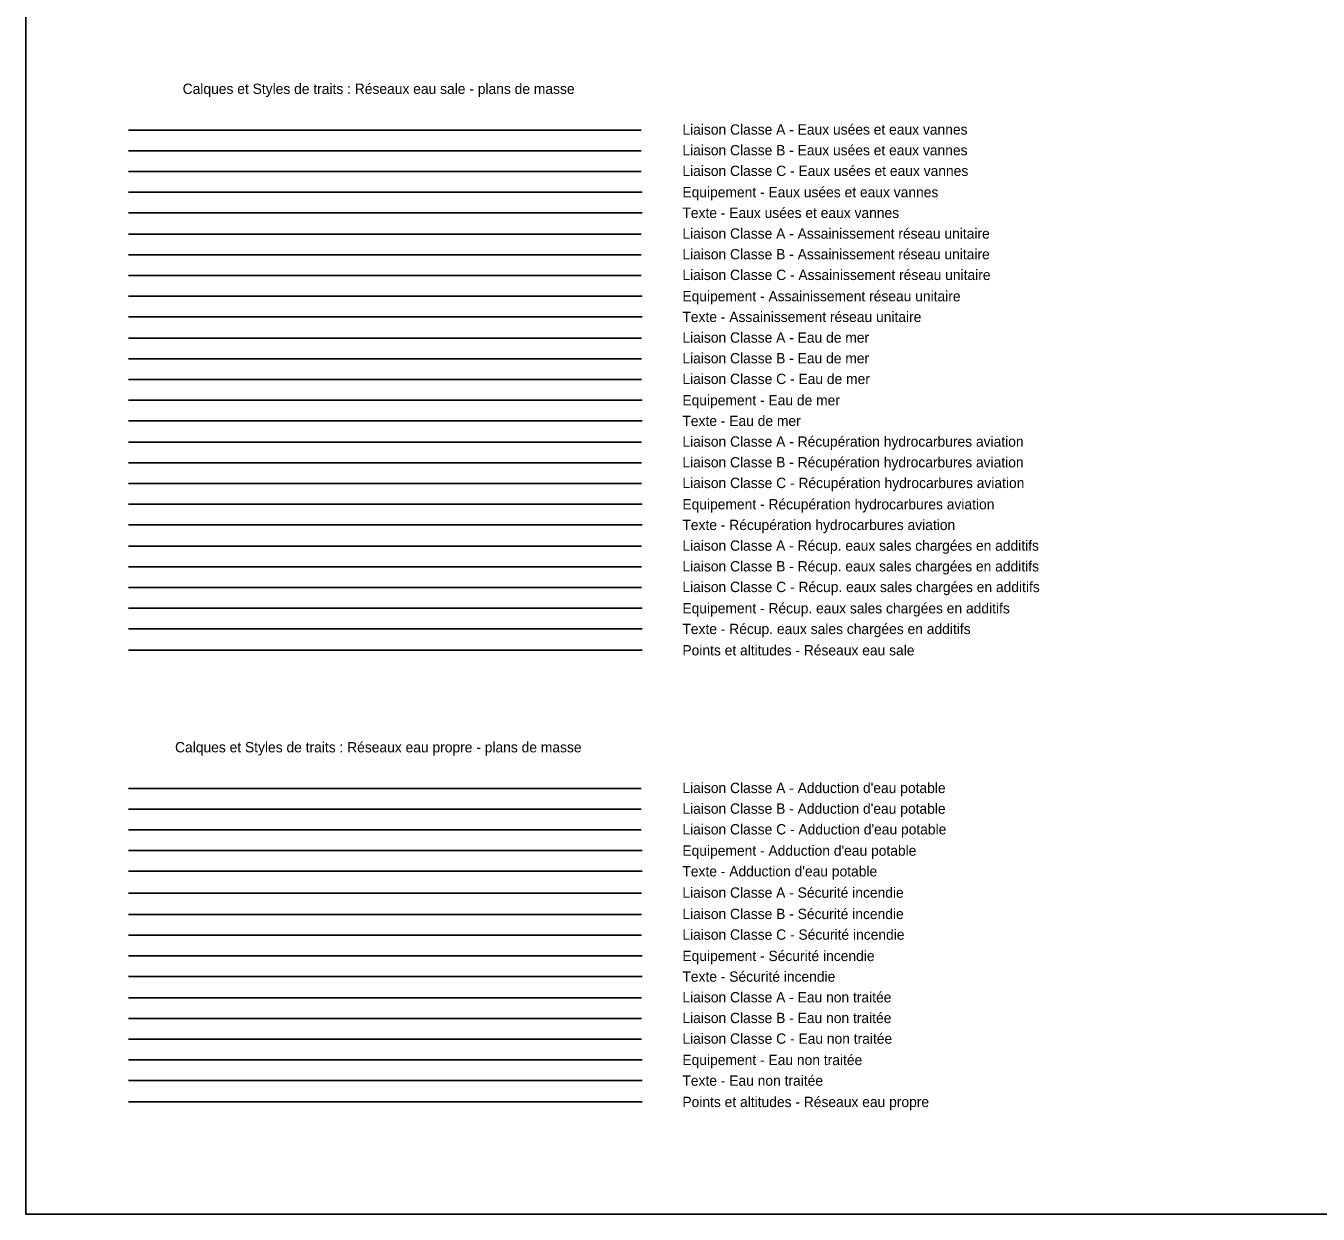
# Model space of a CAD drawing. Extents: x 703432 to 707394, y 7057985 to 7059523.
# Drawn here: x 707199.5 to 707262, y 7058419.6 to 7058477 of the extents above; entities that cross this region are included whole.
import ezdxf

# ---------------------------------------------------------------- set-up
doc = ezdxf.new("R2010")
doc.units = 0
for name, color, linetype in [('DH_CADRE -CARTOUCHE', 7, 'Continuous'), ('R_EPR_AEP_CANALISATION_CL_A', 7, 'Continuous'), ('R_EPR_AEP_CANALISATION_CL_B', 7, 'Continuous'), ('R_EPR_AEP_CANALISATION_CL_C', 7, 'Continuous'), ('R_EPR_AEP_EQUIP', 7, 'Continuous'), ('R_EPR_AEP_TEXTE', 7, 'Continuous'), ('R_EPR_EAU_NON_TRAITEE_CANALISATION_CL_A', 7, 'Continuous'), ('R_EPR_EAU_NON_TRAITEE_CANALISATION_CL_B', 7, 'Continuous'), ('R_EPR_EAU_NON_TRAITEE_CANALISATION_CL_C', 7, 'Continuous'), ('R_EPR_EAU_NON_TRAITEE_EQUIP', 7, 'Continuous'), ('R_EPR_EAU_NON_TRAITEE_TEXTE', 7, 'Continuous'), ('R_EPR_EAU_PROPRE_ALT_POINT', 7, 'Continuous'), ('R_EPR_INCENDIE_CANALISATION_CL_A', 7, 'Continuous'), ('R_EPR_INCENDIE_CANALISATION_CL_B', 7, 'Continuous'), ('R_EPR_INCENDIE_CANALISATION_CL_C', 7, 'Continuous'), ('R_EPR_INCENDIE_EQUIP', 7, 'Continuous'), ('R_EPR_INCENDIE_TEXTE', 7, 'Continuous'), ('R_ES_EAU_SALE_ALT_POINT', 7, 'Continuous'), ('R_ES_EU_CANALISATION_CL_A', 7, 'Continuous'), ('R_ES_EU_CANALISATION_CL_B', 7, 'Continuous'), ('R_ES_EU_CANALISATION_CL_C', 7, 'Continuous'), ('R_ES_EU_EQUIP', 7, 'Continuous'), ('R_ES_EU_TEXTE', 7, 'Continuous'), ('R_ES_HYDROCARB_CANA_CL_A', 7, 'Continuous'), ('R_ES_HYDROCARB_CANA_CL_B', 7, 'Continuous'), ('R_ES_HYDROCARB_CANA_CL_C', 7, 'Continuous'), ('R_ES_HYDROCARB_EQUIP', 7, 'Continuous'), ('R_ES_HYDROCARB_TEXTE', 7, 'Continuous'), ('R_ES_INCENDIE_CANA_CL_A', 7, 'Continuous'), ('R_ES_INCENDIE_CANA_CL_B', 7, 'Continuous'), ('R_ES_INCENDIE_CANA_CL_C', 7, 'Continuous'), ('R_ES_INCENDIE_EQUIP', 7, 'Continuous'), ('R_ES_INCENDIE_TEXTE', 7, 'Continuous'), ('R_ES_MER_CANALISATION_CL_A', 7, 'Continuous'), ('R_ES_MER_CANALISATION_CL_B', 7, 'Continuous'), ('R_ES_MER_CANALISATION_CL_C', 7, 'Continuous'), ('R_ES_MER_EQUIP', 7, 'Continuous'), ('R_ES_MER_TEXTE', 7, 'Continuous'), ('R_ES_UNITAIRE_CANALISATION_CL_A', 7, 'Continuous'), ('R_ES_UNITAIRE_CANALISATION_CL_B', 7, 'Continuous'), ('R_ES_UNITAIRE_CANALISATION_CL_C', 7, 'Continuous'), ('R_ES_UNITAIRE_EQUIP', 7, 'Continuous'), ('R_ES_UNITAIRE_TEXTE', 7, 'Continuous')]:
    doc.layers.add(name, color=color, linetype=linetype)

msp = doc.modelspace()

# ---------------------------------------------------------------- linework, layer by layer
at = {"layer": 'DH_CADRE -CARTOUCHE'}
msp.add_lwpolyline([(707199.469, 7058644.551), (707324.469, 7058644.551), (707324.469, 7058419.551), (707199.469, 7058419.551)], close=True, dxfattribs=at)
at = {"layer": 'R_EPR_AEP_CANALISATION_CL_A'}
msp.add_line((707204.439, 7058440.135), (707229.225, 7058440.135), dxfattribs=at)
at = {"layer": 'R_EPR_AEP_CANALISATION_CL_B'}
msp.add_line((707204.439, 7058439.135), (707229.225, 7058439.135), dxfattribs=at)
at = {"layer": 'R_EPR_AEP_CANALISATION_CL_C'}
msp.add_line((707204.439, 7058438.135), (707229.225, 7058438.135), dxfattribs=at)
at = {"layer": 'R_EPR_AEP_EQUIP'}
msp.add_line((707204.439, 7058437.135), (707229.269, 7058437.135), dxfattribs=at)
at = {"layer": 'R_EPR_AEP_TEXTE'}
msp.add_line((707204.439, 7058436.135), (707229.269, 7058436.135), dxfattribs=at)
at = {"layer": 'R_EPR_EAU_NON_TRAITEE_CANALISATION_CL_A'}
msp.add_line((707204.439, 7058430.011), (707229.24, 7058430.011), dxfattribs=at)
at = {"layer": 'R_EPR_EAU_NON_TRAITEE_CANALISATION_CL_B'}
msp.add_line((707204.439, 7058429.011), (707229.24, 7058429.011), dxfattribs=at)
at = {"layer": 'R_EPR_EAU_NON_TRAITEE_CANALISATION_CL_C'}
msp.add_line((707204.439, 7058428.011), (707229.24, 7058428.011), dxfattribs=at)
at = {"layer": 'R_EPR_EAU_NON_TRAITEE_EQUIP'}
msp.add_line((707204.439, 7058427.011), (707229.269, 7058427.011), dxfattribs=at)
at = {"layer": 'R_EPR_EAU_NON_TRAITEE_TEXTE'}
msp.add_line((707204.439, 7058426.011), (707229.269, 7058426.011), dxfattribs=at)
at = {"layer": 'R_EPR_EAU_PROPRE_ALT_POINT'}
msp.add_line((707204.439, 7058424.98), (707229.269, 7058424.98), dxfattribs=at)
at = {"layer": 'R_EPR_INCENDIE_CANALISATION_CL_A'}
msp.add_line((707204.439, 7058435.073), (707229.24, 7058435.073), dxfattribs=at)
at = {"layer": 'R_EPR_INCENDIE_CANALISATION_CL_B'}
msp.add_line((707204.439, 7058434.042), (707229.24, 7058434.042), dxfattribs=at)
at = {"layer": 'R_EPR_INCENDIE_CANALISATION_CL_C'}
msp.add_line((707204.439, 7058433.042), (707229.24, 7058433.042), dxfattribs=at)
at = {"layer": 'R_EPR_INCENDIE_EQUIP'}
msp.add_line((707204.439, 7058432.042), (707229.269, 7058432.042), dxfattribs=at)
at = {"layer": 'R_EPR_INCENDIE_TEXTE'}
msp.add_line((707204.439, 7058431.042), (707229.269, 7058431.042), dxfattribs=at)
at = {"layer": 'R_ES_EAU_SALE_ALT_POINT'}
msp.add_line((707204.439, 7058446.825), (707229.269, 7058446.825), dxfattribs=at)
at = {"layer": 'R_ES_EU_CANALISATION_CL_A'}
msp.add_line((707204.439, 7058471.98), (707229.225, 7058471.98), dxfattribs=at)
at = {"layer": 'R_ES_EU_CANALISATION_CL_B'}
msp.add_line((707204.439, 7058470.98), (707229.225, 7058470.98), dxfattribs=at)
at = {"layer": 'R_ES_EU_CANALISATION_CL_C'}
msp.add_line((707204.439, 7058469.98), (707229.225, 7058469.98), dxfattribs=at)
at = {"layer": 'R_ES_EU_EQUIP'}
msp.add_line((707204.439, 7058468.98), (707229.269, 7058468.98), dxfattribs=at)
at = {"layer": 'R_ES_EU_TEXTE'}
msp.add_line((707204.439, 7058467.98), (707229.269, 7058467.98), dxfattribs=at)
at = {"layer": 'R_ES_HYDROCARB_CANA_CL_A'}
msp.add_line((707204.439, 7058456.887), (707229.24, 7058456.887), dxfattribs=at)
at = {"layer": 'R_ES_HYDROCARB_CANA_CL_B'}
msp.add_line((707204.439, 7058455.887), (707229.24, 7058455.887), dxfattribs=at)
at = {"layer": 'R_ES_HYDROCARB_CANA_CL_C'}
msp.add_line((707204.439, 7058454.887), (707229.24, 7058454.887), dxfattribs=at)
at = {"layer": 'R_ES_HYDROCARB_EQUIP'}
msp.add_line((707204.439, 7058453.887), (707229.269, 7058453.887), dxfattribs=at)
at = {"layer": 'R_ES_HYDROCARB_TEXTE'}
msp.add_line((707204.439, 7058452.887), (707229.269, 7058452.887), dxfattribs=at)
at = {"layer": 'R_ES_INCENDIE_CANA_CL_A'}
msp.add_line((707204.439, 7058451.856), (707229.24, 7058451.856), dxfattribs=at)
at = {"layer": 'R_ES_INCENDIE_CANA_CL_B'}
msp.add_line((707204.439, 7058450.856), (707229.24, 7058450.856), dxfattribs=at)
at = {"layer": 'R_ES_INCENDIE_CANA_CL_C'}
msp.add_line((707204.439, 7058449.856), (707229.24, 7058449.856), dxfattribs=at)
at = {"layer": 'R_ES_INCENDIE_EQUIP'}
msp.add_line((707204.439, 7058448.856), (707229.269, 7058448.856), dxfattribs=at)
at = {"layer": 'R_ES_INCENDIE_TEXTE'}
msp.add_line((707204.439, 7058447.856), (707229.269, 7058447.856), dxfattribs=at)
at = {"layer": 'R_ES_MER_CANALISATION_CL_A'}
msp.add_line((707204.439, 7058461.918), (707229.24, 7058461.918), dxfattribs=at)
at = {"layer": 'R_ES_MER_CANALISATION_CL_B'}
msp.add_line((707204.439, 7058460.918), (707229.24, 7058460.918), dxfattribs=at)
at = {"layer": 'R_ES_MER_CANALISATION_CL_C'}
msp.add_line((707204.439, 7058459.918), (707229.24, 7058459.918), dxfattribs=at)
at = {"layer": 'R_ES_MER_EQUIP'}
msp.add_line((707204.439, 7058458.918), (707229.269, 7058458.918), dxfattribs=at)
at = {"layer": 'R_ES_MER_TEXTE'}
msp.add_line((707204.439, 7058457.918), (707229.269, 7058457.918), dxfattribs=at)
at = {"layer": 'R_ES_UNITAIRE_CANALISATION_CL_A'}
msp.add_line((707204.439, 7058466.949), (707229.225, 7058466.949), dxfattribs=at)
at = {"layer": 'R_ES_UNITAIRE_CANALISATION_CL_B'}
msp.add_line((707204.439, 7058465.949), (707229.225, 7058465.949), dxfattribs=at)
at = {"layer": 'R_ES_UNITAIRE_CANALISATION_CL_C'}
msp.add_line((707204.439, 7058464.949), (707229.225, 7058464.949), dxfattribs=at)
at = {"layer": 'R_ES_UNITAIRE_EQUIP'}
msp.add_line((707204.439, 7058463.949), (707229.269, 7058463.949), dxfattribs=at)
at = {"layer": 'R_ES_UNITAIRE_TEXTE'}
msp.add_line((707204.439, 7058462.949), (707229.269, 7058462.949), dxfattribs=at)

# ---------------------------------------------------------------- texts
at = {"layer": 'DH_CADRE -CARTOUCHE'}
for s, p in [(' Calques et Styles de traits : Réseaux eau sale - plans de masse', (707206.868, 7058473.73)), (' Calques et Styles de traits : Réseaux eau propre - plans de masse', (707206.499, 7058441.885))]:
    msp.add_text(s, height=0.5, dxfattribs=at).set_placement(p)
at = {"layer": 'R_EPR_AEP_CANALISATION_CL_A'}
msp.add_text("Liaison Classe A - Adduction d'eau potable ", height=0.5, dxfattribs=at).set_placement((707231.222, 7058439.916))
at = {"layer": 'R_EPR_AEP_CANALISATION_CL_B'}
msp.add_text("Liaison Classe B - Adduction d'eau potable ", height=0.5, dxfattribs=at).set_placement((707231.222, 7058438.916))
at = {"layer": 'R_EPR_AEP_CANALISATION_CL_C'}
msp.add_text("Liaison Classe C - Adduction d'eau potable ", height=0.5, dxfattribs=at).set_placement((707231.222, 7058437.916))
at = {"layer": 'R_EPR_AEP_EQUIP'}
msp.add_text("Equipement - Adduction d'eau potable ", height=0.5, dxfattribs=at).set_placement((707231.222, 7058436.885))
at = {"layer": 'R_EPR_AEP_TEXTE'}
msp.add_text("Texte - Adduction d'eau potable ", height=0.5, dxfattribs=at).set_placement((707231.222, 7058435.885))
at = {"layer": 'R_EPR_EAU_NON_TRAITEE_CANALISATION_CL_A'}
msp.add_text('Liaison Classe A - Eau non traitée', height=0.5, dxfattribs=at).set_placement((707231.222, 7058429.792))
at = {"layer": 'R_EPR_EAU_NON_TRAITEE_CANALISATION_CL_B'}
msp.add_text('Liaison Classe B - Eau non traitée', height=0.5, dxfattribs=at).set_placement((707231.222, 7058428.792))
at = {"layer": 'R_EPR_EAU_NON_TRAITEE_CANALISATION_CL_C'}
msp.add_text('Liaison Classe C - Eau non traitée', height=0.5, dxfattribs=at).set_placement((707231.222, 7058427.792))
at = {"layer": 'R_EPR_EAU_NON_TRAITEE_EQUIP'}
msp.add_text('Equipement - Eau non traitée', height=0.5, dxfattribs=at).set_placement((707231.222, 7058426.761))
at = {"layer": 'R_EPR_EAU_NON_TRAITEE_TEXTE'}
msp.add_text('Texte - Eau non traitée', height=0.5, dxfattribs=at).set_placement((707231.222, 7058425.761))
at = {"layer": 'R_EPR_EAU_PROPRE_ALT_POINT'}
msp.add_text('Points et altitudes - Réseaux eau propre', height=0.5, dxfattribs=at).set_placement((707231.222, 7058424.73))
at = {"layer": 'R_EPR_INCENDIE_CANALISATION_CL_A'}
msp.add_text('Liaison Classe A - Sécurité incendie', height=0.5, dxfattribs=at).set_placement((707231.222, 7058434.854))
at = {"layer": 'R_EPR_INCENDIE_CANALISATION_CL_B'}
msp.add_text('Liaison Classe B - Sécurité incendie', height=0.5, dxfattribs=at).set_placement((707231.222, 7058433.823))
at = {"layer": 'R_EPR_INCENDIE_CANALISATION_CL_C'}
msp.add_text('Liaison Classe C - Sécurité incendie', height=0.5, dxfattribs=at).set_placement((707231.222, 7058432.823))
at = {"layer": 'R_EPR_INCENDIE_EQUIP'}
msp.add_text('Equipement - Sécurité incendie', height=0.5, dxfattribs=at).set_placement((707231.222, 7058431.792))
at = {"layer": 'R_EPR_INCENDIE_TEXTE'}
msp.add_text('Texte - Sécurité incendie', height=0.5, dxfattribs=at).set_placement((707231.222, 7058430.792))
at = {"layer": 'R_ES_EAU_SALE_ALT_POINT'}
msp.add_text('Points et altitudes - Réseaux eau sale', height=0.5, dxfattribs=at).set_placement((707231.222, 7058446.575))
at = {"layer": 'R_ES_EU_CANALISATION_CL_A'}
msp.add_text('Liaison Classe A - Eaux usées et eaux vannes', height=0.5, dxfattribs=at).set_placement((707231.222, 7058471.761))
at = {"layer": 'R_ES_EU_CANALISATION_CL_B'}
msp.add_text('Liaison Classe B - Eaux usées et eaux vannes', height=0.5, dxfattribs=at).set_placement((707231.222, 7058470.761))
at = {"layer": 'R_ES_EU_CANALISATION_CL_C'}
msp.add_text('Liaison Classe C - Eaux usées et eaux vannes', height=0.5, dxfattribs=at).set_placement((707231.222, 7058469.761))
at = {"layer": 'R_ES_EU_EQUIP'}
msp.add_text('Equipement - Eaux usées et eaux vannes', height=0.5, dxfattribs=at).set_placement((707231.222, 7058468.73))
at = {"layer": 'R_ES_EU_TEXTE'}
msp.add_text('Texte - Eaux usées et eaux vannes', height=0.5, dxfattribs=at).set_placement((707231.222, 7058467.73))
at = {"layer": 'R_ES_HYDROCARB_CANA_CL_A'}
msp.add_text('Liaison Classe A - Récupération hydrocarbures aviation', height=0.5, dxfattribs=at).set_placement((707231.222, 7058456.668))
at = {"layer": 'R_ES_HYDROCARB_CANA_CL_B'}
msp.add_text('Liaison Classe B - Récupération hydrocarbures aviation', height=0.5, dxfattribs=at).set_placement((707231.222, 7058455.668))
at = {"layer": 'R_ES_HYDROCARB_CANA_CL_C'}
msp.add_text('Liaison Classe C - Récupération hydrocarbures aviation', height=0.5, dxfattribs=at).set_placement((707231.222, 7058454.668))
at = {"layer": 'R_ES_HYDROCARB_EQUIP'}
msp.add_text('Equipement - Récupération hydrocarbures aviation', height=0.5, dxfattribs=at).set_placement((707231.222, 7058453.637))
at = {"layer": 'R_ES_HYDROCARB_TEXTE'}
msp.add_text('Texte - Récupération hydrocarbures aviation', height=0.5, dxfattribs=at).set_placement((707231.222, 7058452.637))
at = {"layer": 'R_ES_INCENDIE_CANA_CL_A'}
msp.add_text('Liaison Classe A - Récup. eaux sales chargées en additifs', height=0.5, dxfattribs=at).set_placement((707231.222, 7058451.637))
at = {"layer": 'R_ES_INCENDIE_CANA_CL_B'}
msp.add_text('Liaison Classe B - Récup. eaux sales chargées en additifs', height=0.5, dxfattribs=at).set_placement((707231.222, 7058450.637))
at = {"layer": 'R_ES_INCENDIE_CANA_CL_C'}
msp.add_text('Liaison Classe C - Récup. eaux sales chargées en additifs', height=0.5, dxfattribs=at).set_placement((707231.222, 7058449.637))
at = {"layer": 'R_ES_INCENDIE_EQUIP'}
msp.add_text('Equipement - Récup. eaux sales chargées en additifs', height=0.5, dxfattribs=at).set_placement((707231.222, 7058448.606))
at = {"layer": 'R_ES_INCENDIE_TEXTE'}
msp.add_text('Texte - Récup. eaux sales chargées en additifs', height=0.5, dxfattribs=at).set_placement((707231.222, 7058447.606))
at = {"layer": 'R_ES_MER_CANALISATION_CL_A'}
msp.add_text('Liaison Classe A - Eau de mer', height=0.5, dxfattribs=at).set_placement((707231.222, 7058461.699))
at = {"layer": 'R_ES_MER_CANALISATION_CL_B'}
msp.add_text('Liaison Classe B - Eau de mer', height=0.5, dxfattribs=at).set_placement((707231.222, 7058460.699))
at = {"layer": 'R_ES_MER_CANALISATION_CL_C'}
msp.add_text('Liaison Classe C - Eau de mer', height=0.5, dxfattribs=at).set_placement((707231.222, 7058459.699))
at = {"layer": 'R_ES_MER_EQUIP'}
msp.add_text('Equipement - Eau de mer', height=0.5, dxfattribs=at).set_placement((707231.222, 7058458.668))
at = {"layer": 'R_ES_MER_TEXTE'}
msp.add_text('Texte - Eau de mer', height=0.5, dxfattribs=at).set_placement((707231.222, 7058457.668))
at = {"layer": 'R_ES_UNITAIRE_CANALISATION_CL_A'}
msp.add_text('Liaison Classe A - Assainissement réseau unitaire', height=0.5, dxfattribs=at).set_placement((707231.222, 7058466.73))
at = {"layer": 'R_ES_UNITAIRE_CANALISATION_CL_B'}
msp.add_text('Liaison Classe B - Assainissement réseau unitaire', height=0.5, dxfattribs=at).set_placement((707231.222, 7058465.73))
at = {"layer": 'R_ES_UNITAIRE_CANALISATION_CL_C'}
msp.add_text('Liaison Classe C - Assainissement réseau unitaire', height=0.5, dxfattribs=at).set_placement((707231.222, 7058464.73))
at = {"layer": 'R_ES_UNITAIRE_EQUIP'}
msp.add_text('Equipement - Assainissement réseau unitaire', height=0.5, dxfattribs=at).set_placement((707231.222, 7058463.699))
at = {"layer": 'R_ES_UNITAIRE_TEXTE'}
msp.add_text('Texte - Assainissement réseau unitaire', height=0.5, dxfattribs=at).set_placement((707231.222, 7058462.699))

doc.saveas('drawing.dxf')
